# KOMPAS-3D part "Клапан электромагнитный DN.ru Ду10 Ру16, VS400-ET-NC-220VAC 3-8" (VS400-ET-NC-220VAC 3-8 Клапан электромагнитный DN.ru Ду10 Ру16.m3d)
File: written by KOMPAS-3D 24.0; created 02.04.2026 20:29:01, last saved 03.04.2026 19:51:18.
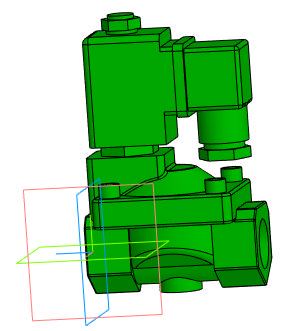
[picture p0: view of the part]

Document properties: Автор: artio; Полное имя файла: C:\Users\artio\OneDrive\Рабочий стол\Клапан электромагнитный DN.ru\VS400-ET-NC-220VAC 3-8 Клапан электромагнитный DN.ru Ду10 Ру16.m3d

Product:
- Body: Тело 1  | qty 1
    Масса: 1.030062
- Part/product: Клапан электромагнитный DN.ru Ду10 Ру16  | designation VS400-ET-NC-220VAC 3-8
    Масса: 0.797
    Раздел спецификации: Прочие изделия
    Примечание: D130-04690
    additional columns: ef56311e-7521-43dc-8291-0e6108b3d81d; VS400-ET-NC-220VAC 3-8; artio; c; Шероховатость не задана; Да

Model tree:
1. Операция без истории:1

Expressions: VS400-ET-NC-220VAC 3-8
